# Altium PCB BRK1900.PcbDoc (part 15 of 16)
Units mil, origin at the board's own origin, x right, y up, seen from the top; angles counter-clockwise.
Board outline 8858.27 x 5905.51 mil, 10 copper layers (L1-TOP, L2-GND, L3-PWR, L4-GND, L5-PWR, L6-PWR, L7-GND, L8-SIG, L9-GND, L10-BOT), stack 48.824 mil thick; 456 components, 571 nets, 2296 pads, 2416 vias.
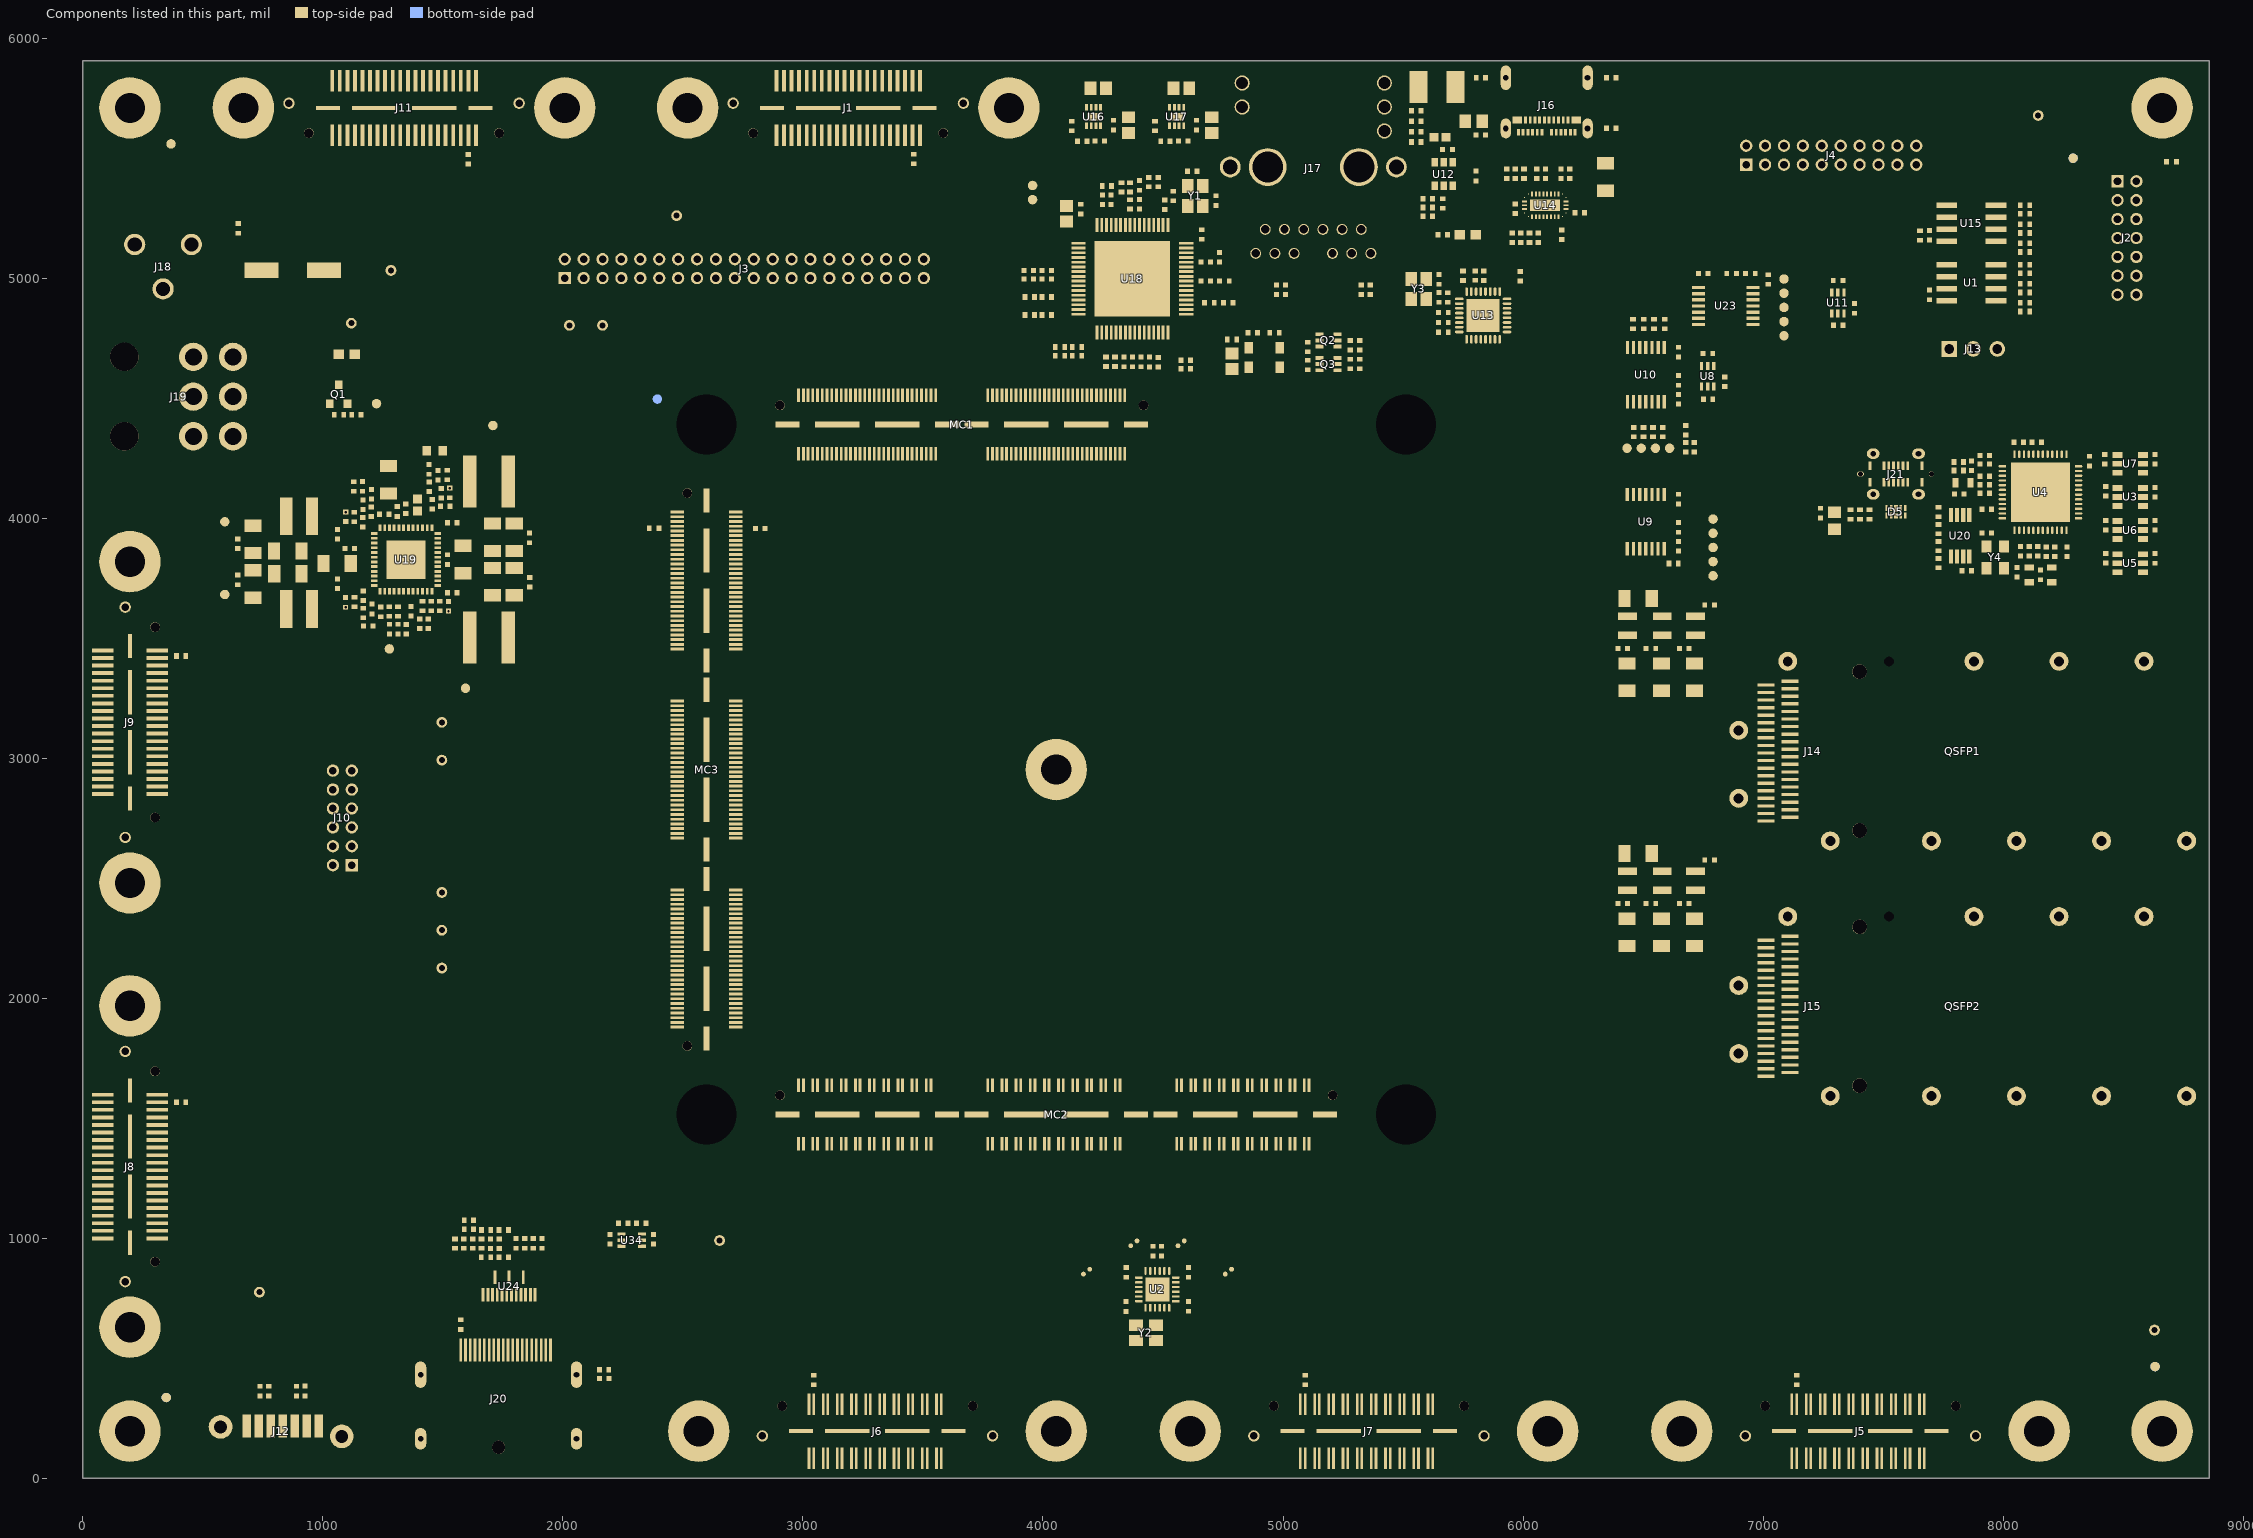
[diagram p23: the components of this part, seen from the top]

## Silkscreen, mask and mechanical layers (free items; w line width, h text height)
Top Overlay:
  circle w22: c201,4873 r11
  region: 5688.98,1078.74 5027.98,1078.74 5027.98,763.78 5688.98,763.78
  lines w4.72: 29.53,4062 738.19,4062 738.19,4822.83 561.02,4822.83 561.02,5374.02 255.91,5374.02 ; 1968.5,1373 1416,1373 1416,1100 2054,1100 2054,1318.9 ; 4749.57,4586.61 1968.5,4586.61 1968.5,1318.9 6377.95,1318.9 6377.95,2373.59 ; 4825.23,4586.61 6377.95,4586.61 6377.95,3478.77 ; 6377.95,2415.78 6377.95,3436.58 ; 6911,5623 7213,5623 ; 7358,5622 7501,5622 ; 255.91,5374.02 29.53,5374.02 255.91,5374.02
  lines w15.75: 139,4873 201,4873 ; 187.32,4835.41 ccw(c201,4873) 187.32,4910.59 ; 241,4873 289,4873
  text "USB 3.0" at 6664.97,5877.3 h100 r180
  text "+1.8V" at 7535,5747 h30 r270
  text "DGND" at 7617,5727 h30 r270
  text "PS CONFIG" at 7007.46,5683.39 h75
  text "DGND" at 7223,5600 h30
  text "VDCIN:" at 30,5467 h30
  text "PROG_B" at 6899.61,5413.38 h30 r270
  text "ERROR_OUT" at 6978.35,5413.38 h30 r270
  text "ERROR_STATUS" at 7057.09,5413.38 h30 r270
  text "SRST_B" at 7135.83,5413.38 h30 r270
  text "DONE" at 7214.57,5413.38 h30 r270
  text "MODE3" at 7303.15,5413.38 h30 r270
  text "MODE2" at 7381.89,5413.38 h30 r270
  text "MODE1" at 7460.63,5413.38 h30 r270
  text "MODE0" at 7539.37,5413.38 h30 r270
  text "INIT_B" at 7618.11,5413.38 h30 r270
  text "6-15 VDC" at 41,5396 h80
  text "+1.8V" at 8659,5391.74 h30
  text "TMS" at 8659,5307.74 h30
  text "JTAG" at 8295.93,5285.05 h75 r270
  text "TCK" at 8659,5231.74 h30
  text "TDO" at 8659,5150.74 h30
  text "I/O BREAKOUT" at 2532.24,5127.95 h40
  text "TDI" at 8659,5075.74 h30
  text "SRST_B" at 8659,4912.74 h30
  text "-" at 380.99,4907.99 h70 r180
  text "Ethernet" at 5341.75,4898.96 h100 r180
  text "+" at 126,4834 h70 r90
  text "DGND" at 7755.91,4645.67 h30 r270
  text "SDA" at 7850.39,4645.67 h30 r270
  text "SCL" at 7948.82,4645.67 h30 r270
  text "USB JTAG" at 7361.03,4315.19 h75
  text "PWR" at 449,4207 h60 r270
  text "GND" at 608.5,4207 h60 r270
  text "QSFP1" at 7034.81,3485.55 h100
  text "I/O BREAKOUT" at 1174,2989.35 h40 r270
  text "QSFP2" at 7034.81,2422.56 h100
  text "'.Part_Number' / '.PCB_Revision'XX" at 3328.36,787.25 h40
  text "DisplayPort / Source" at 1944.88,609.15 h100
  text "SATA" at 668.66,438.31 h100
Dimensions:
  text ":::" at 6846.99,5979 h40 r180
  text ":::" at 2640,5943 h40
  text ":::" at -69,4019 h40 r270
  text ":::" at 8929,3929.69 h40 r90
  text ":::" at -73,1844 h40 r270
  text ":::" at 8929,1220.47 h40 r90
  text ":::" at 2528,-62 h40
  text ":::" at 6350,-67 h40
  text "All dimensions in mm unless otherwise specified" at 9247,-80 h50
Outline:
  the board outline again, w7.87
Mechanical:
  lines w3.94: 1968.46,1318.79 1968.46,4586.51 ; 1968.5,1318.9 6377.95,1318.9 6377.95,4586.61 1968.5,4586.61
Fab Notes:
  drawing of 180 lines, arcs and shapes, not listed
  text "LAYER STACKUP TABLE" at 9476.38,9166.3 h50
  text "M" at 12034.15,9045.9 h73.62
  text "a" at 12088.96,9045.88 h73.62
  text "t" at 12122.69,9045.88 h73.62
  text "e" at 12143.78,9045.88 h73.62
  text "r" at 12181.73,9045.9 h73.62
  text "i" at 12207.03,9045.9 h73.62
  text "a" at 12223.89,9045.88 h73.62
  text "l" at 12257.62,9045.9 h73.62
  text "S" at 13065.26,9042.91 h73.62
  text "i" at 13094.78,9042.91 h73.62
  text "n" at 13111.64,9042.91 h73.62
  text "g" at 13145.43,9042.93 h73.62
  text "l" at 13174.89,9042.91 h73.62
  text "e" at 13191.76,9042.91 h73.62
  text "-" at 13225.49,9042.91 h73.62
  text "E" at 13246.57,9042.92 h73.62
  text "n" at 13276.09,9042.91 h73.62
  text "d" at 13309.82,9042.91 h73.62
  text "e" at 13343.55,9042.91 h73.62
  text "d" at 13377.28,9042.91 h73.62
  text "D" at 13885.94,9042.92 h73.62
  text "i" at 13923.89,9042.91 h73.62
  text "f" at 13940.76,9042.91 h73.62
  text "f" at 13961.84,9042.91 h73.62
  text "e" at 13982.92,9042.91 h73.62
  text "r" at 14016.65,9042.91 h73.62
  text "e" at 14037.74,9042.91 h73.62
  text "n" at 14071.47,9042.91 h73.62
  text "t" at 14105.2,9042.96 h73.62
  text "i" at 14126.29,9042.91 h73.62
  text "a" at 14143.15,9042.91 h73.62
  text "l" at 14172.67,9042.91 h73.62
  text "D" at 14235.26,9042.92 h73.62
  text "i" at 14273.21,9042.91 h73.62
  text "f" at 14290.07,9042.91 h73.62
  text "f" at 14311.16,9042.91 h73.62
  text "e" at 14332.24,9042.91 h73.62
  text "r" at 14365.97,9042.91 h73.62
  text "e" at 14387.05,9042.91 h73.62
  text "n" at 14420.79,9042.91 h73.62
  text "t" at 14454.52,9042.96 h73.62
  text "i" at 14475.6,9042.91 h73.62
  text "a" at 14492.47,9042.91 h73.62
  text "l" at 14521.98,9042.91 h73.62
  text "D" at 14626.66,9042.92 h73.62
  text "i" at 14664.61,9042.91 h73.62
  text "f" at 14681.47,9042.91 h73.62
  text "f" at 14702.56,9042.91 h73.62
  text "e" at 14723.64,9042.91 h73.62
  text "r" at 14757.37,9042.91 h73.62
  text "e" at 14778.46,9042.91 h73.62
  text "n" at 14812.19,9042.91 h73.62
  text "t" at 14845.92,9042.96 h73.62
  text "i" at 14867,9042.91 h73.62
  text "a" at 14883.87,9042.91 h73.62
  text "l" at 14913.39,9042.91 h73.62
  text "D" at 14975.98,9042.92 h73.62
  text "i" at 15013.92,9042.91 h73.62
  text "f" at 15030.79,9042.91 h73.62
  text "f" at 15051.87,9042.91 h73.62
  text "e" at 15072.96,9042.91 h73.62
  text "r" at 15106.69,9042.91 h73.62
  text "e" at 15127.77,9042.91 h73.62
  text "n" at 15161.5,9042.91 h73.62
  text "t" at 15195.24,9042.96 h73.62
  text "i" at 15216.32,9042.91 h73.62
  text "a" at 15233.19,9042.91 h73.62
  text "l" at 15262.7,9042.91 h73.62
  text "P" at 12029.94,8961.56 h73.62
  text "r" at 12072.1,8961.56 h73.62
  text "e" at 12097.4,8961.55 h73.62
  text "s" at 12135.35,8961.55 h73.62
  text "s" at 12169.08,8961.55 h73.62
  text "e" at 12202.82,8961.55 h73.62
  text "d" at 12240.77,8961.55 h73.62
  text "C" at 12375.05,8958.59 h73.62
  text "o" at 12408.78,8958.58 h73.62
  text "p" at 12442.51,8958.59 h73.62
  text "p" at 12476.24,8958.59 h73.62
  text "e" at 12509.98,8958.58 h73.62
  text "r" at 12543.71,8958.58 h73.62
  text "T" at 13170.48,8958.58 h73.62
  text "r" at 13199.99,8958.58 h73.62
  text "a" at 13221.07,8958.58 h73.62
  text "c" at 13250.59,8958.61 h73.62
  text "e" at 13275.89,8958.58 h73.62
  text "S" at 13460.87,8958.58 h73.62
  text "i" at 13490.39,8958.58 h73.62
  text "n" at 13507.25,8958.58 h73.62
  text "g" at 13541.04,8958.6 h73.62
  text "l" at 13570.5,8958.58 h73.62
  text "e" at 13587.37,8958.58 h73.62
  text "-" at 13621.1,8958.58 h73.62
  text "E" at 13642.18,8958.59 h73.62
  text "n" at 13671.7,8958.58 h73.62
  text "d" at 13705.43,8958.58 h73.62
  text "e" at 13739.16,8958.58 h73.62
  text "d" at 13772.9,8958.58 h73.62
  text "T" at 13970.11,8958.58 h73.62
  text "r" at 13999.63,8958.58 h73.62
  text "a" at 14020.71,8958.58 h73.62
  text "c" at 14050.23,8958.61 h73.62
  text "e" at 14075.53,8958.58 h73.62
  text "T" at 14315.22,8958.58 h73.62
  text "r" at 14344.74,8958.58 h73.62
  text "a" at 14365.82,8958.58 h73.62
  text "c" at 14395.34,8958.61 h73.62
  text "e" at 14420.64,8958.58 h73.62
  text "T" at 14710.83,8958.58 h73.62
  text "r" at 14740.35,8958.58 h73.62
  text "a" at 14761.43,8958.58 h73.62
  text "c" at 14790.95,8958.61 h73.62
  text "e" at 14816.25,8958.58 h73.62
  text "T" at 15055.94,8958.58 h73.62
  text "r" at 15085.46,8958.58 h73.62
  text "a" at 15106.54,8958.58 h73.62
  text "c" at 15136.05,8958.61 h73.62
  text "e" at 15161.35,8958.58 h73.62
  text "G" at 10295.99,8877.29 h73.62
  text "e" at 10346.58,8877.22 h73.62
  text "r" at 10384.53,8877.23 h73.62
  text "b" at 10409.83,8877.22 h73.62
  text "e" at 10447.78,8877.22 h73.62
  text "r" at 10485.73,8877.23 h73.62
  text "M" at 11697.46,8877.23 h73.62
  text "a" at 11752.27,8877.22 h73.62
  text "t" at 11786.01,8877.22 h73.62
  text "e" at 11807.09,8877.22 h73.62
  text "r" at 11845.04,8877.23 h73.62
  text "i" at 11870.34,8877.23 h73.62
  text "a" at 11887.2,8877.22 h73.62
  text "l" at 11920.93,8877.23 h73.62
  text "T" at 12000.48,8877.23 h73.62
  text "h" at 12042.64,8877.23 h73.62
  text "i" at 12080.59,8877.23 h73.62
  text "c" at 12097.46,8877.22 h73.62
  text "k" at 12131.19,8877.23 h73.62
  text "n" at 12164.92,8877.23 h73.62
  text "e" at 12202.87,8877.22 h73.62
  text "s" at 12240.82,8877.22 h73.62
  text "s" at 12274.55,8877.22 h73.62
  text "T" at 12341.38,8874.24 h73.62
  text "h" at 12370.89,8874.24 h73.62
  text "i" at 12404.63,8874.24 h73.62
  text "c" at 12421.49,8874.28 h73.62
  text "k" at 12446.79,8874.24 h73.62
  text "n" at 12476.31,8874.24 h73.62
  text "e" at 12510.04,8874.24 h73.62
  text "s" at 12543.77,8874.24 h73.62
  text "s" at 12569.07,8874.24 h73.62
  text "C" at 12707.53,8874.26 h73.62
  text "o" at 12741.26,8874.24 h73.62
  text "p" at 12774.99,8874.25 h73.62
  text "p" at 12808.72,8874.25 h73.62
  text "e" at 12842.46,8874.24 h73.62
  text "r" at 12876.19,8874.24 h73.62
  text "I" at 13094.72,8874.24 h73.62
  text "m" at 13111.59,8874.24 h73.62
  text "p" at 13162.19,8874.25 h73.62
  text "e" at 13195.92,8874.24 h73.62
  text "d" at 13229.65,8874.24 h73.62
  text "a" at 13263.38,8874.24 h73.62
  text "n" at 13292.9,8874.24 h73.62
  text "c" at 13326.63,8874.28 h73.62
  text "e" at 13351.93,8874.24 h73.62
  text "T" at 13477.71,8874.24 h73.62
  text "r" at 13507.22,8874.24 h73.62
  text "a" at 13528.3,8874.24 h73.62
  text "c" at 13557.82,8874.28 h73.62
  text "e" at 13583.12,8874.24 h73.62
  text "W" at 13629.5,8874.24 h73.62
  text "i" at 13688.53,8874.24 h73.62
  text "d" at 13705.4,8874.24 h73.62
  text "t" at 13739.13,8874.3 h73.62
  text "h" at 13760.21,8874.24 h73.62
  text "I" at 13894.36,8874.24 h73.62
  text "m" at 13911.23,8874.24 h73.62
  text "p" at 13961.82,8874.25 h73.62
  text "e" at 13995.56,8874.24 h73.62
  text "d" at 14029.29,8874.24 h73.62
  text "a" at 14063.02,8874.24 h73.62
  text "n" at 14092.54,8874.24 h73.62
  text "c" at 14126.27,8874.28 h73.62
  text "e" at 14151.57,8874.24 h73.62
  text "W" at 14214.21,8874.24 h73.62
  text "i" at 14273.25,8874.24 h73.62
  text "d" at 14290.11,8874.24 h73.62
  text "t" at 14323.84,8874.3 h73.62
  text "h" at 14344.93,8874.24 h73.62
  text "/" at 14378.69,8874.29 h73.62
  text "S" at 14403.96,8874.24 h73.62
  text "p" at 14433.48,8874.25 h73.62
  text "a" at 14467.21,8874.24 h73.62
  text "c" at 14496.72,8874.28 h73.62
  text "e" at 14522.02,8874.24 h73.62
  text "I" at 14635.08,8874.24 h73.62
  text "m" at 14651.94,8874.24 h73.62
  text "p" at 14702.54,8874.25 h73.62
  text "e" at 14736.27,8874.24 h73.62
  text "d" at 14770.01,8874.24 h73.62
  text "a" at 14803.74,8874.24 h73.62
  text "n" at 14833.25,8874.24 h73.62
  text "c" at 14866.99,8874.28 h73.62
  text "e" at 14892.29,8874.24 h73.62
  text "W" at 14954.93,8874.24 h73.62
  text "i" at 15013.96,8874.24 h73.62
  text "d" at 15030.83,8874.24 h73.62
  text "t" at 15064.56,8874.3 h73.62
  text "h" at 15085.65,8874.24 h73.62
  text "/" at 15119.41,8874.29 h73.62
  text "S" at 15144.68,8874.24 h73.62
  text "p" at 15174.19,8874.25 h73.62
  text "a" at 15207.93,8874.24 h73.62
  text "c" at 15237.44,8874.28 h73.62
  text "e" at 15262.74,8874.24 h73.62
  text "L" at 9487.93,8792.9 h73.62
  text "a" at 9525.88,8792.89 h73.62
  text "y" at 9559.61,8792.9 h73.62
  text "e" at 9589.13,8792.89 h73.62
  text "r" at 9627.08,8792.9 h73.62
  text "L" at 9698.36,8792.9 h73.62
  text "a" at 9736.31,8792.89 h73.62
  text "y" at 9770.04,8792.9 h73.62
  text "e" at 9799.56,8792.89 h73.62
  text "r" at 9837.51,8792.9 h73.62
  text "N" at 9879.67,8792.9 h73.62
  text "a" at 9926.05,8792.89 h73.62
  text "m" at 9959.79,8792.9 h73.62
  text "e" at 10010.39,8792.89 h73.62
  text "L" at 10295.99,8792.9 h73.62
  text "a" at 10333.93,8792.89 h73.62
  text "y" at 10367.67,8792.9 h73.62
  text "e" at 10397.18,8792.89 h73.62
  text "r" at 10435.13,8792.9 h73.62
  text "M" at 10548.5,8792.9 h73.62
  text "a" at 10603.32,8792.89 h73.62
  text "t" at 10637.05,8792.89 h73.62
  text "e" at 10658.13,8792.89 h73.62
  text "r" at 10696.08,8792.9 h73.62
  text "i" at 10721.38,8792.9 h73.62
  text "a" at 10738.25,8792.89 h73.62
  text "l" at 10771.98,8792.9 h73.62
  text "T" at 10805.71,8792.9 h73.62
  text "y" at 10847.88,8792.9 h73.62
  text "p" at 10877.39,8792.92 h73.62
  text "e" at 10915.34,8792.89 h73.62
  text "M" at 10981.99,8792.9 h73.62
  text "a" at 11036.81,8792.89 h73.62
  text "t" at 11070.54,8792.89 h73.62
  text "e" at 11091.62,8792.89 h73.62
  text "r" at 11129.57,8792.9 h73.62
  text "i" at 11154.87,8792.9 h73.62
  text "a" at 11171.74,8792.89 h73.62
  text "l" at 11205.47,8792.9 h73.62
  text "C" at 11239.2,8792.9 h73.62
  text "o" at 11285.58,8792.89 h73.62
  text "n" at 11323.53,8792.9 h73.62
  text "s" at 11361.48,8792.89 h73.62
  text "t" at 11395.21,8792.89 h73.62
  text "r" at 11416.3,8792.9 h73.62
  text "u" at 11441.6,8792.89 h73.62
  text "c" at 11479.54,8792.89 h73.62
  text "t" at 11513.28,8792.89 h73.62
  text "i" at 11534.36,8792.9 h73.62
  text "o" at 11551.23,8792.89 h73.62
  text "n" at 11589.17,8792.9 h73.62
  text "E" at 11663.79,8792.9 h73.62
  text "r" at 11705.95,8792.9 h73.62
  text "(" at 11748.12,8792.9 h73.62
  text "1" at 11769.2,8792.9 h73.62
  text "G" at 11819.8,8792.95 h73.62
  text "H" at 11870.4,8792.9 h73.62
  text "z" at 11916.78,8792.9 h73.62
  text ")" at 11950.51,8792.9 h73.62
  text "(" at 12093.07,8792.9 h73.62
  text "m" at 12114.15,8792.9 h73.62
  text "i" at 12164.75,8792.9 h73.62
  text "l" at 12181.62,8792.9 h73.62
  text ")" at 12198.48,8792.9 h73.62
  text "(" at 12404.51,8789.92 h73.62
  text "u" at 12425.59,8789.91 h73.62
  text "m" at 12459.32,8789.91 h73.62
  text ")" at 12509.89,8789.92 h73.62
  text "W" at 12648.61,8789.91 h73.62
  text "e" at 12707.64,8789.91 h73.62
  text "i" at 12741.37,8789.91 h73.62
  text "g" at 12758.29,8789.94 h73.62
  text "h" at 12787.75,8789.91 h73.62
  text "t" at 12821.49,8789.96 h73.62
  text "(" at 12855.22,8789.92 h73.62
  text "o" at 12876.3,8789.91 h73.62
  text "z" at 12910.03,8789.93 h73.62
  text ")" at 12935.3,8789.92 h73.62
  text "(" at 13145.22,8789.92 h73.62
  text "o" at 13166.31,8789.91 h73.62
  text "h" at 13200.04,8789.91 h73.62
  text "m" at 13233.77,8789.91 h73.62
  text "s" at 13284.37,8789.91 h73.62
  text ")" at 13309.64,8789.92 h73.62
  text "(" at 13557.67,8789.92 h73.62
  text "m" at 13578.75,8789.91 h73.62
  text "i" at 13629.35,8789.91 h73.62
  text "l" at 13646.22,8789.91 h73.62
  text "s" at 13663.08,8789.91 h73.62
  text ")" at 13688.35,8789.92 h73.62
  text "(" at 13944.86,8789.92 h73.62
  text "o" at 13965.95,8789.91 h73.62
  text "h" at 13999.68,8789.91 h73.62
  text "m" at 14033.41,8789.91 h73.62
  text "s" at 14084.01,8789.91 h73.62
  text ")" at 14109.27,8789.92 h73.62
  text "(" at 14311.01,8789.92 h73.62
  text "m" at 14332.1,8789.91 h73.62
  text "i" at 14382.69,8789.91 h73.62
  text "l" at 14399.56,8789.91 h73.62
  text "s" at 14416.43,8789.91 h73.62
  text ")" at 14441.69,8789.92 h73.62
  text "(" at 14685.58,8789.92 h73.62
  text "o" at 14706.66,8789.91 h73.62
  text "h" at 14740.4,8789.91 h73.62
  text "m" at 14774.13,8789.91 h73.62
  text "s" at 14824.73,8789.91 h73.62
  text ")" at 14849.99,8789.92 h73.62
  text "(" at 15051.73,8789.92 h73.62
  text "m" at 15072.81,8789.91 h73.62
  text "i" at 15123.41,8789.91 h73.62
  text "l" at 15140.28,8789.91 h73.62
  text "s" at 15157.14,8789.91 h73.62
  text ")" at 15182.41,8789.92 h73.62
  text "O" at 9698.36,8670.61 h69.53
  text "v" at 9748.96,8670.62 h69.53
  text "e" at 9778.48,8670.64 h69.53
  text "r" at 9812.21,8670.62 h69.53
  text "l" at 9833.29,8670.62 h69.53
  text "a" at 9845.94,8670.64 h69.53
  text "y" at 9879.67,8670.62 h69.53
  text "T" at 9926.05,8670.62 h69.53
  text "o" at 9964,8670.64 h69.53
  text "p" at 9997.74,8670.61 h69.53
  text "G" at 10295.99,8670.61 h69.53
  text "T" at 10342.37,8670.62 h69.53
  text "O" at 10380.32,8670.61 h69.53
  text "S" at 10548.5,8670.61 h69.53
  text "i" at 10590.67,8670.62 h69.53
  text "l" at 10603.32,8670.62 h69.53
  text "k" at 10616.02,8670.62 h69.53
  text "s" at 10645.48,8670.64 h69.53
  text "c" at 10679.22,8670.64 h69.53
  text "r" at 10712.95,8670.62 h69.53
  text "e" at 10734.03,8670.64 h69.53
  text "e" at 10767.76,8670.64 h69.53
  text "n" at 10801.5,8670.62 h69.53
  text "S" at 9698.36,8586.27 h69.53
  text "o" at 9740.53,8586.31 h69.53
  text "l" at 9774.26,8586.29 h69.53
  text "d" at 9786.91,8586.31 h69.53
  text "e" at 9820.64,8586.31 h69.53
  text "r" at 9854.37,8586.29 h69.53
  text "M" at 9892.32,8586.29 h69.53
  text "a" at 9938.7,8586.31 h69.53
  text "s" at 9972.44,8586.31 h69.53
  text "k" at 10006.22,8586.29 h69.53
  text "T" at 10052.55,8586.29 h69.53
  text "o" at 10090.5,8586.31 h69.53
  text "p" at 10124.23,8586.27 h69.53
  text "G" at 10295.99,8586.27 h69.53
  text "T" at 10342.37,8586.29 h69.53
  text "S" at 10380.32,8586.27 h69.53
  text "S" at 10548.5,8586.27 h69.53
  text "o" at 10590.67,8586.31 h69.53
  text "l" at 10624.4,8586.29 h69.53
  text "d" at 10637.05,8586.31 h69.53
  text "e" at 10670.78,8586.31 h69.53
  text "r" at 10704.52,8586.29 h69.53
  text "R" at 10742.46,8586.29 h69.53
  text "e" at 10788.85,8586.31 h69.53
  text "s" at 10822.58,8586.31 h69.53
  text "i" at 10856.31,8586.29 h69.53
  text "s" at 10868.96,8586.31 h69.53
  text "t" at 10902.69,8586.31 h69.53
  text "3" at 11781.63,8583.34 h73.62
  text "." at 11811.15,8583.3 h73.62
  text "5" at 11828.01,8583.34 h73.62
  text "1" at 9487.93,8501.96 h69.53
  text "L" at 9698.36,8501.96 h69.53
  text "1" at 9732.09,8501.96 h69.53
  text "-" at 9765.83,8501.96 h69.53
  text "T" at 9786.91,8501.96 h69.53
  text "O" at 9824.86,8501.94 h69.53
  text "P" at 9875.46,8501.96 h69.53
  text "G" at 10295.99,8501.94 h69.53
  text "T" at 10342.37,8501.96 h69.53
  text "L" at 10380.32,8501.96 h69.53
  text "C" at 10548.5,8501.94 h69.53
  text "o" at 10594.89,8501.98 h69.53
  text "p" at 10628.62,8501.94 h69.53
  text "p" at 10662.35,8501.94 h69.53
  text "e" at 10696.08,8501.98 h69.53
  text "r" at 10729.81,8501.96 h69.53
  text "3" at 12400.3,8499.01 h73.62
  text "0" at 12429.81,8499.01 h73.62
  text "-" at 12459.33,8498.99 h73.62
  text "5" at 12480.41,8499.01 h73.62
  text "0" at 12509.93,8499.01 h73.62
  text "1" at 12644.4,8498.99 h73.62
  text "/" at 12673.95,8499 h73.62
  text "3" at 12699.21,8499.01 h73.62
  text "+" at 12741.38,8498.99 h73.62
  text "p" at 12783.54,8499.03 h73.62
  text "l" at 12817.28,8498.97 h73.62
  text "a" at 12834.14,8499.01 h73.62
  text "t" at 12863.66,8498.99 h73.62
  text "i" at 12884.74,8498.97 h73.62
  text "n" at 12901.61,8498.97 h73.62
  text "g" at 12935.34,8499 h73.62
  text "5" at 13212.56,8499.01 h73.62
  text "0" at 13242.08,8499.01 h73.62
  text "4" at 13582.92,8498.97 h73.62
  text "." at 13612.44,8498.97 h73.62
  text "5" at 13629.3,8499.01 h73.62
  text "5" at 13658.82,8499.01 h73.62
  text "9" at 14007.99,8499.01 h73.62
  text "0" at 14037.51,8499.01 h73.62
  text "4" at 14256.3,8498.97 h73.62
  text "." at 14285.82,8498.97 h73.62
  text "0" at 14302.68,8499.01 h73.62
  text "5" at 14332.2,8499.01 h73.62
  text "/" at 14374.4,8499 h73.62
  text "4" at 14412.31,8498.97 h73.62
  text "." at 14441.83,8498.97 h73.62
  text "9" at 14458.7,8499.01 h73.62
  text "5" at 14488.21,8499.01 h73.62
  text "1" at 14736.08,8498.99 h73.62
  text "0" at 14765.6,8499.01 h73.62
  text "0" at 14795.12,8499.01 h73.62
  text "3" at 14997.02,8499.01 h73.62
  text "." at 15026.53,8498.97 h73.62
  text "3" at 15043.4,8499.01 h73.62
  text "0" at 15072.92,8499.01 h73.62
  text "/" at 15115.12,8499 h73.62
  text "5" at 15153.03,8499.01 h73.62
  text "." at 15182.55,8498.97 h73.62
  text "7" at 15199.41,8498.97 h73.62
  text "0" at 15228.93,8499.01 h73.62
  text "P" at 10548.5,8417.63 h69.53
  text "r" at 10590.67,8417.63 h69.53
  text "e" at 10611.75,8417.64 h69.53
  text "p" at 10645.48,8417.61 h69.53
  text "r" at 10679.22,8417.63 h69.53
  text "e" at 10700.3,8417.64 h69.53
  text "g" at 10734.03,8417.63 h69.53
  text "P" at 10981.99,8414.64 h73.62
  text "P" at 11015.72,8414.64 h73.62
  text "(" at 11049.46,8414.68 h73.62
  text "1" at 11070.54,8414.66 h73.62
  text "0" at 11100.05,8414.67 h73.62
  text "8" at 11129.57,8414.67 h73.62
  text "0" at 11159.09,8414.67 h73.62
  text ")" at 11188.62,8414.68 h73.62
  text "R" at 11209.69,8414.64 h73.62
  text "C" at 11243.42,8414.64 h73.62
  text "7" at 11277.15,8414.64 h73.62
  text "1" at 11306.67,8414.66 h73.62
  text "3" at 11781.63,8414.67 h73.62
  text "." at 11811.15,8414.64 h73.62
  text "9" at 11828.01,8414.67 h73.62
  text "2" at 12088.86,8414.66 h73.62
  text "." at 12118.38,8414.64 h73.62
  text "9" at 12135.24,8414.67 h73.62
  text "7" at 12164.76,8414.64 h73.62
  text "2" at 12194.27,8414.66 h73.62
  text "2" at 9487.95,8333.3 h69.53
  text "L" at 9698.36,8333.3 h69.53
  text "2" at 9732.11,8333.3 h69.53
  text "-" at 9765.83,8333.3 h69.53
  text "G" at 9786.91,8333.28 h69.53
  text "N" at 9833.29,8333.3 h69.53
  text "D" at 9875.46,8333.3 h69.53
  text "G" at 10295.99,8333.28 h69.53
  text "1" at 10342.37,8333.3 h69.53
  text "C" at 10548.5,8333.28 h69.53
  text "o" at 10594.89,8333.31 h69.53
  text "p" at 10628.62,8333.28 h69.53
  text "p" at 10662.35,8333.28 h69.53
  text "e" at 10696.08,8333.31 h69.53
  text "r" at 10729.81,8333.3 h69.53
  text "1" at 12438.18,8330.33 h73.62
  text "5" at 12467.69,8330.34 h73.62
  text "1" at 12762.24,8330.33 h73.62
  text "/" at 12791.79,8330.33 h73.62
  text "2" at 12817.05,8330.33 h73.62
  text "C" at 10548.5,8248.95 h69.53
  text "o" at 10594.89,8248.98 h69.53
  text "r" at 10628.62,8248.97 h69.53
  text "e" at 10649.7,8248.98 h69.53
  text "2" at 10981.99,8246 h73.62
  text "*" at 11011.51,8245.96 h73.62
  text "7" at 11041.02,8245.98 h73.62
  text "6" at 11070.54,8246.01 h73.62
  text "2" at 11100.05,8246 h73.62
  text "8" at 11129.57,8246.01 h73.62
  text "(" at 11171.74,8246.02 h73.62
  text "R" at 11192.82,8245.98 h73.62
  text "C" at 11226.55,8245.98 h73.62
  text "5" at 11260.28,8246.01 h73.62
  text "0" at 11289.8,8246.01 h73.62
  text ")" at 11319.33,8246.02 h73.62
  text "4" at 11781.63,8245.98 h73.62
  text "." at 11811.15,8245.98 h73.62
  text "6" at 11828.01,8246.01 h73.62
  text "1" at 12072.03,8246 h73.62
  text "6" at 12101.54,8246.01 h73.62
  text "." at 12131.06,8245.98 h73.62
  text "0" at 12147.92,8246.01 h73.62
  text "0" at 12177.44,8246.01 h73.62
  text "0" at 12206.95,8246.01 h73.62
  text "3" at 9487.93,8164.6 h69.53
  text "L" at 9698.36,8164.64 h69.53
  text "3" at 9732.09,8164.6 h69.53
  text "-" at 9765.83,8164.64 h69.53
  text "S" at 9786.91,8164.62 h69.53
  text "I" at 9829.07,8164.64 h69.53
  text "G" at 9841.72,8164.62 h69.53
  text "1" at 9888.11,8164.64 h69.53
  text "G" at 10295.99,8164.62 h69.53
  text "2" at 10342.38,8164.64 h69.53
  text "C" at 10548.5,8164.62 h69.53
  text "o" at 10594.89,8164.65 h69.53
  text "p" at 10628.62,8164.62 h69.53
  text "p" at 10662.35,8164.62 h69.53
  text "e" at 10696.08,8164.65 h69.53
  text "r" at 10729.81,8164.64 h69.53
  text "1" at 12438.18,8161.66 h73.62
  text "5" at 12467.69,8161.68 h73.62
  text "1" at 12762.24,8161.66 h73.62
  text "/" at 12791.79,8161.67 h73.62
  text "2" at 12817.05,8161.66 h73.62
  text "P" at 10548.5,8080.31 h69.53
  text "r" at 10590.67,8080.31 h69.53
  text "e" at 10611.75,8080.32 h69.53
  text "p" at 10645.48,8080.29 h69.53
  text "r" at 10679.22,8080.31 h69.53
  text "e" at 10700.3,8080.32 h69.53
  text "g" at 10734.03,8080.3 h69.53
  text "P" at 10981.99,8077.32 h73.62
  text "P" at 11015.72,8077.32 h73.62
  text "(" at 11049.46,8077.36 h73.62
  text "1" at 11070.54,8077.33 h73.62
  text "0" at 11100.05,8077.35 h73.62
  text "8" at 11129.57,8077.35 h73.62
  text "0" at 11159.09,8077.35 h73.62
  text ")" at 11188.62,8077.36 h73.62
  text "R" at 11209.69,8077.32 h73.62
  text "C" at 11243.42,8077.32 h73.62
  text "7" at 11277.15,8077.32 h73.62
  text "1" at 11306.67,8077.33 h73.62
  text "3" at 11781.63,8077.35 h73.62
  text "." at 11811.15,8077.32 h73.62
  text "9" at 11828.01,8077.35 h73.62
  text "3" at 12088.86,8077.35 h73.62
  text "." at 12118.38,8077.32 h73.62
  text "0" at 12135.24,8077.35 h73.62
  text "5" at 12164.76,8077.35 h73.62
  text "5" at 12194.27,8077.35 h73.62
  text "4" at 9487.93,7995.98 h69.53
  text "L" at 9698.36,7995.98 h69.53
  text "4" at 9732.09,7995.98 h69.53
  text "-" at 9765.83,7995.98 h69.53
  text "G" at 9786.91,7995.96 h69.53
  text "N" at 9833.29,7995.98 h69.53
  text "D" at 9875.46,7995.98 h69.53
  text "G" at 10295.99,7995.96 h69.53
  text "3" at 10342.37,7995.94 h69.53
  text "C" at 10548.5,7995.96 h69.53
  text "o" at 10594.89,7995.99 h69.53
  text "p" at 10628.62,7995.96 h69.53
  text "p" at 10662.35,7995.96 h69.53
  text "e" at 10696.08,7995.99 h69.53
  text "r" at 10729.81,7995.98 h69.53
  text "1" at 12438.18,7993 h73.62
  text "5" at 12467.69,7993.02 h73.62
  text "1" at 12762.24,7993 h73.62
  text "/" at 12791.79,7993.01 h73.62
  text "2" at 12817.05,7993 h73.62
  text "C" at 10548.5,7911.63 h69.53
  text "o" at 10594.89,7911.66 h69.53
  text "r" at 10628.62,7911.64 h69.53
  text "e" at 10649.7,7911.66 h69.53
  text "2" at 10981.99,7908.67 h73.62
  text "*" at 11011.51,7908.64 h73.62
  text "7" at 11041.02,7908.65 h73.62
  text "6" at 11070.54,7908.69 h73.62
  text "2" at 11100.05,7908.67 h73.62
  text "8" at 11129.57,7908.69 h73.62
  text "(" at 11171.74,7908.7 h73.62
  text "R" at 11192.82,7908.65 h73.62
  text "C" at 11226.55,7908.65 h73.62
  text "5" at 11260.28,7908.69 h73.62
  text "0" at 11289.8,7908.69 h73.62
  text ")" at 11319.33,7908.7 h73.62
  text "4" at 11781.63,7908.65 h73.62
  text "." at 11811.15,7908.65 h73.62
  text "6" at 11828.01,7908.69 h73.62
  text "1" at 12072.03,7908.67 h73.62
  text "6" at 12101.54,7908.69 h73.62
  text "." at 12131.06,7908.65 h73.62
  text "0" at 12147.92,7908.69 h73.62
  text "0" at 12177.44,7908.69 h73.62
  text "0" at 12206.95,7908.69 h73.62
  text "5" at 9487.93,7827.3 h69.53
  text "L" at 9698.36,7827.31 h69.53
  text "5" at 9732.09,7827.3 h69.53
  text "-" at 9765.83,7827.32 h69.53
  text "P" at 9786.91,7827.31 h69.53
  text "W" at 9829.07,7827.31 h69.53
  text "R" at 9892.32,7827.31 h69.53
  text "1" at 9938.7,7827.31 h69.53
  text "G" at 10295.99,7827.3 h69.53
  text "4" at 10342.37,7827.31 h69.53
  text "C" at 10548.5,7827.3 h69.53
  text "o" at 10594.89,7827.33 h69.53
  text "p" at 10628.62,7827.3 h69.53
  text "p" at 10662.35,7827.3 h69.53
  text "e" at 10696.08,7827.33 h69.53
  text "r" at 10729.81,7827.31 h69.53
  text "1" at 12438.18,7824.34 h73.62
  text "5" at 12467.69,7824.36 h73.62
  text "1" at 12762.24,7824.34 h73.62
  text "/" at 12791.79,7824.35 h73.62
  text "2" at 12817.05,7824.34 h73.62
  text "P" at 10548.5,7742.98 h69.53
  text "r" at 10590.67,7742.98 h69.53
  text "e" at 10611.75,7743 h69.53
  text "p" at 10645.48,7742.96 h69.53
  text "r" at 10679.22,7742.98 h69.53
  text "e" at 10700.3,7743 h69.53
  text "g" at 10734.03,7742.98 h69.53
  text "P" at 10981.99,7739.99 h73.62
  text "P" at 11015.72,7739.99 h73.62
  text "(" at 11049.46,7740.04 h73.62
  text "1" at 11070.54,7740.01 h73.62
  text "0" at 11100.05,7740.03 h73.62
  text "8" at 11129.57,7740.03 h73.62
  text "0" at 11159.09,7740.03 h73.62
  text ")" at 11188.62,7740.04 h73.62
  text "R" at 11209.69,7739.99 h73.62
  text "C" at 11243.42,7739.99 h73.62
  text "7" at 11277.15,7739.99 h73.62
  text "1" at 11306.67,7740.01 h73.62
  text "3" at 11781.63,7740.03 h73.62
  text "." at 11811.15,7739.99 h73.62
  text "9" at 11828.01,7740.03 h73.62
  text "3" at 12088.86,7740.03 h73.62
  text "." at 12118.38,7739.99 h73.62
  text "2" at 12135.24,7740.01 h73.62
  text "9" at 12164.76,7740.03 h73.62
  text "1" at 12194.27,7740.01 h73.62
  text "6" at 9487.93,7658.63 h69.53
  text "L" at 9698.36,7658.65 h69.53
  text "6" at 9732.09,7658.63 h69.53
  text "-" at 9765.83,7658.65 h69.53
  text "P" at 9786.91,7658.65 h69.53
  text "W" at 9829.07,7658.65 h69.53
  text "R" at 9892.32,7658.65 h69.53
  text "2" at 9938.72,7658.65 h69.53
  text "G" at 10295.99,7658.63 h69.53
  text "5" at 10342.37,7658.63 h69.53
  text "C" at 10548.5,7658.63 h69.53
  text "o" at 10594.89,7658.67 h69.53
  text "p" at 10628.62,7658.63 h69.53
  text "p" at 10662.35,7658.63 h69.53
  text "e" at 10696.08,7658.67 h69.53
  text "r" at 10729.81,7658.65 h69.53
  text "1" at 12438.18,7655.68 h73.62
  text "5" at 12467.69,7655.7 h73.62
  text "1" at 12762.24,7655.68 h73.62
  text "/" at 12791.79,7655.69 h73.62
  text "2" at 12817.05,7655.68 h73.62
  text "C" at 10548.5,7574.3 h69.53
  text "o" at 10594.89,7574.33 h69.53
  text "r" at 10628.62,7574.32 h69.53
  text "e" at 10649.7,7574.33 h69.53
  text "2" at 10981.99,7571.35 h73.62
  text "*" at 11011.51,7571.31 h73.62
  text "7" at 11041.02,7571.33 h73.62
  text "6" at 11070.54,7571.36 h73.62
  text "2" at 11100.05,7571.35 h73.62
  text "8" at 11129.57,7571.36 h73.62
  text "(" at 11171.74,7571.37 h73.62
  text "R" at 11192.82,7571.33 h73.62
  text "C" at 11226.55,7571.33 h73.62
  text "5" at 11260.28,7571.36 h73.62
  text "0" at 11289.8,7571.36 h73.62
  text ")" at 11319.33,7571.37 h73.62
  text "4" at 11781.63,7571.33 h73.62
  text "." at 11811.15,7571.33 h73.62
  text "6" at 11828.01,7571.36 h73.62
  text "1" at 12072.03,7571.35 h73.62
  text "6" at 12101.54,7571.36 h73.62
  text "." at 12131.06,7571.33 h73.62
  text "0" at 12147.92,7571.36 h73.62
  text "0" at 12177.44,7571.36 h73.62
  text "0" at 12206.95,7571.36 h73.62
  text "7" at 9487.93,7489.99 h69.53
  text "L" at 9698.36,7489.99 h69.53
  text "7" at 9732.09,7489.99 h69.53
  text "-" at 9765.83,7489.99 h69.53
  text "G" at 9786.91,7489.97 h69.53
  text "N" at 9833.29,7489.99 h69.53
  text "D" at 9875.46,7489.99 h69.53
  text "G" at 10295.99,7489.97 h69.53
  text "6" at 10342.37,7489.97 h69.53
  text "C" at 10548.5,7489.97 h69.53
  text "o" at 10594.89,7490 h69.53
  text "p" at 10628.62,7489.97 h69.53
  text "p" at 10662.35,7489.97 h69.53
  text "e" at 10696.08,7490 h69.53
  text "r" at 10729.81,7489.99 h69.53
  text "1" at 12438.18,7487.02 h73.62
  text "5" at 12467.69,7487.03 h73.62
  text "1" at 12762.24,7487.02 h73.62
  text "/" at 12791.79,7487.02 h73.62
  text "2" at 12817.05,7487.02 h73.62
  text "P" at 10548.5,7405.66 h69.53
  text "r" at 10590.67,7405.66 h69.53
  text "e" at 10611.75,7405.67 h69.53
  text "p" at 10645.48,7405.64 h69.53
  text "r" at 10679.22,7405.66 h69.53
  text "e" at 10700.3,7405.67 h69.53
  text "g" at 10734.03,7405.66 h69.53
  text "P" at 10981.99,7402.67 h73.62
  text "P" at 11015.72,7402.67 h73.62
  text "(" at 11049.46,7402.71 h73.62
  text "1" at 11070.54,7402.69 h73.62
  text "0" at 11100.05,7402.7 h73.62
  text "8" at 11129.57,7402.7 h73.62
  text "0" at 11159.09,7402.7 h73.62
  text ")" at 11188.62,7402.71 h73.62
  text "R" at 11209.69,7402.67 h73.62
  text "C" at 11243.42,7402.67 h73.62
  text "7" at 11277.15,7402.67 h73.62
  text "1" at 11306.67,7402.69 h73.62
  text "3" at 11781.63,7402.7 h73.62
  text "." at 11811.15,7402.67 h73.62
  text "9" at 11828.01,7402.7 h73.62
  text "3" at 12088.86,7402.7 h73.62
  text "." at 12118.38,7402.67 h73.62
  text "0" at 12135.24,7402.7 h73.62
  text "5" at 12164.76,7402.7 h73.62
  text "5" at 12194.27,7402.7 h73.62
  text "8" at 9487.93,7321.31 h69.53
  text "L" at 9698.36,7321.33 h69.53
  text "8" at 9732.09,7321.31 h69.53
  text "-" at 9765.83,7321.33 h69.53
  text "S" at 9786.91,7321.31 h69.53
  text "I" at 9829.07,7321.33 h69.53
  text "G" at 9841.72,7321.31 h69.53
  text "2" at 9888.12,7321.33 h69.53
  text "G" at 10295.99,7321.31 h69.53
  text "7" at 10342.37,7321.33 h69.53
  text "C" at 10548.5,7321.31 h69.53
  text "o" at 10594.89,7321.34 h69.53
  text "p" at 10628.62,7321.31 h69.53
  text "p" at 10662.35,7321.31 h69.53
  text "e" at 10696.08,7321.34 h69.53
  text "r" at 10729.81,7321.33 h69.53
  text "1" at 12438.18,7318.35 h73.62
  text "5" at 12467.69,7318.37 h73.62
  text "1" at 12762.24,7318.35 h73.62
  text "/" at 12791.79,7318.36 h73.62
  text "2" at 12817.05,7318.35 h73.62
  text "5" at 13212.56,7318.37 h73.62
  text "0" at 13242.08,7318.37 h73.62
  text "4" at 13582.92,7318.34 h73.62
  text "." at 13612.44,7318.34 h73.62
  text "0" at 13629.3,7318.37 h73.62
  text "5" at 13658.82,7318.37 h73.62
  text "1" at 14736.08,7318.35 h73.62
  text "0" at 14765.6,7318.37 h73.62
  text "0" at 14795.12,7318.37 h73.62
  text "3" at 14997.02,7318.37 h73.62
  text "." at 15026.53,7318.34 h73.62
  text "1" at 15043.4,7318.35 h73.62
  text "5" at 15072.92,7318.37 h73.62
  text "/" at 15115.12,7318.36 h73.62
  text "5" at 15153.03,7318.37 h73.62
  text "." at 15182.55,7318.34 h73.62
  text "8" at 15199.41,7318.37 h73.62
  text "5" at 15228.93,7318.37 h73.62
  text "C" at 10548.5,7236.98 h69.53
  text "o" at 10594.89,7237.01 h69.53
  text "r" at 10628.62,7237 h69.53
  text "e" at 10649.7,7237.01 h69.53
  text "2" at 10981.99,7234.02 h73.62
  text "*" at 11011.51,7233.99 h73.62
  text "7" at 11041.02,7234.01 h73.62
  text "6" at 11070.54,7234.04 h73.62
  text "2" at 11100.05,7234.02 h73.62
  text "8" at 11129.57,7234.04 h73.62
  text "(" at 11171.74,7234.05 h73.62
  text "R" at 11192.82,7234.01 h73.62
  text "C" at 11226.55,7234.01 h73.62
  text "5" at 11260.28,7234.04 h73.62
  text "0" at 11289.8,7234.04 h73.62
  text ")" at 11319.33,7234.05 h73.62
  text "4" at 11781.63,7234.01 h73.62
  text "." at 11811.15,7234.01 h73.62
  text "6" at 11828.01,7234.04 h73.62
  text "1" at 12072.03,7234.02 h73.62
  text "6" at 12101.54,7234.04 h73.62
  text "." at 12131.06,7234.01 h73.62
  text "0" at 12147.92,7234.04 h73.62
  text "0" at 12177.44,7234.04 h73.62
  text "0" at 12206.95,7234.04 h73.62
  text "9" at 9487.93,7152.65 h69.53
  text "L" at 9698.36,7152.66 h69.53
  text "9" at 9732.09,7152.65 h69.53
  text "-" at 9765.83,7152.67 h69.53
  text "G" at 9786.91,7152.65 h69.53
  text "N" at 9833.29,7152.66 h69.53
  text "D" at 9875.46,7152.66 h69.53
  text "G" at 10295.99,7152.65 h69.53
  text "8" at 10342.37,7152.65 h69.53
  text "C" at 10548.5,7152.65 h69.53
  text "o" at 10594.89,7152.68 h69.53
  text "p" at 10628.62,7152.65 h69.53
  text "p" at 10662.35,7152.65 h69.53
  text "e" at 10696.08,7152.68 h69.53
  text "r" at 10729.81,7152.66 h69.53
  text "1" at 12438.18,7149.69 h73.62
  text "5" at 12467.69,7149.71 h73.62
  text "1" at 12762.24,7149.69 h73.62
  text "/" at 12791.79,7149.7 h73.62
  text "2" at 12817.05,7149.69 h73.62
  text "P" at 10548.5,7068.33 h69.53
  text "r" at 10590.67,7068.33 h69.53
  text "e" at 10611.75,7068.35 h69.53
  text "p" at 10645.48,7068.32 h69.53
  text "r" at 10679.22,7068.33 h69.53
  text "e" at 10700.3,7068.35 h69.53
  text "g" at 10734.03,7068.33 h69.53
  text "P" at 10981.99,7065.34 h73.62
  text "P" at 11015.72,7065.34 h73.62
  text "(" at 11049.46,7065.39 h73.62
  text "1" at 11070.54,7065.36 h73.62
  text "0" at 11100.05,7065.38 h73.62
  text "8" at 11129.57,7065.38 h73.62
  text "0" at 11159.09,7065.38 h73.62
  text ")" at 11188.62,7065.39 h73.62
  text "R" at 11209.69,7065.34 h73.62
  text "C" at 11243.42,7065.34 h73.62
  text "7" at 11277.15,7065.34 h73.62
  text "1" at 11306.67,7065.36 h73.62
  text "3" at 11781.63,7065.38 h73.62
  text "." at 11811.15,7065.34 h73.62
  text "9" at 11828.01,7065.38 h73.62
  text "2" at 12088.86,7065.36 h73.62
  text "." at 12118.38,7065.34 h73.62
  text "9" at 12135.24,7065.38 h73.62
  text "7" at 12164.76,7065.34 h73.62
  text "2" at 12194.27,7065.36 h73.62
  text "1" at 9487.93,6984 h69.53
  text "0" at 9521.66,6983.99 h69.53
  text "L" at 9698.36,6984 h69.53
  text "1" at 9732.09,6984 h69.53
  text "0" at 9765.83,6983.99 h69.53
  text "-" at 9799.56,6984.01 h69.53
  text "B" at 9820.64,6984 h69.53
  text "O" at 9862.81,6983.99 h69.53
  text "T" at 9913.41,6984 h69.53
  text "G" at 10295.99,6983.99 h69.53
  text "B" at 10342.37,6984 h69.53
  text "L" at 10384.53,6984 h69.53
  text "C" at 10548.5,6983.99 h69.53
  text "o" at 10594.89,6984.02 h69.53
  text "p" at 10628.62,6983.99 h69.53
  text "p" at 10662.35,6983.99 h69.53
  text "e" at 10696.08,6984.02 h69.53
  text "r" at 10729.81,6984 h69.53
  text "3" at 12400.3,6981.05 h73.62
  text "0" at 12429.81,6981.05 h73.62
  text "-" at 12459.33,6981.03 h73.62
  text "5" at 12480.41,6981.05 h73.62
  text "0" at 12509.93,6981.05 h73.62
  text "1" at 12644.4,6981.03 h73.62
  text "/" at 12673.95,6981.04 h73.62
  text "3" at 12699.21,6981.05 h73.62
  text "+" at 12741.38,6981.03 h73.62
  text "p" at 12783.54,6981.07 h73.62
  text "l" at 12817.28,6981.01 h73.62
  text "a" at 12834.14,6981.05 h73.62
  text "t" at 12863.66,6981.03 h73.62
  text "i" at 12884.74,6981.01 h73.62
  text "n" at 12901.61,6981.01 h73.62
  text "g" at 12935.34,6981.04 h73.62
  text "5" at 13212.56,6981.05 h73.62
  text "0" at 13242.08,6981.05 h73.62
  text "4" at 13582.92,6981.01 h73.62
  text "." at 13612.44,6981.01 h73.62
  text "5" at 13629.3,6981.05 h73.62
  text "5" at 13658.82,6981.05 h73.62
  text "9" at 14007.99,6981.05 h73.62
  text "0" at 14037.51,6981.05 h73.62
  text "4" at 14256.3,6981.01 h73.62
  text "." at 14285.82,6981.01 h73.62
  text "0" at 14302.68,6981.05 h73.62
  text "5" at 14332.2,6981.05 h73.62
  text "/" at 14374.4,6981.04 h73.62
  text "4" at 14412.31,6981.01 h73.62
  text "." at 14441.83,6981.01 h73.62
  text "9" at 14458.7,6981.05 h73.62
  text "5" at 14488.21,6981.05 h73.62
  text "1" at 14736.08,6981.03 h73.62
  text "0" at 14765.6,6981.05 h73.62
  text "0" at 14795.12,6981.05 h73.62
  text "3" at 14997.02,6981.05 h73.62
  text "." at 15026.53,6981.01 h73.62
  text "3" at 15043.4,6981.05 h73.62
  text "0" at 15072.92,6981.05 h73.62
  text "/" at 15115.12,6981.04 h73.62
  text "5" at 15153.03,6981.05 h73.62
  text "." at 15182.55,6981.01 h73.62
  text "7" at 15199.41,6981.01 h73.62
  text "0" at 15228.93,6981.05 h73.62
  text "S" at 9698.36,6899.65 h69.53
  text "o" at 9740.53,6899.69 h69.53
  text "l" at 9774.26,6899.67 h69.53
  text "d" at 9786.91,6899.69 h69.53
  text "e" at 9820.64,6899.69 h69.53
  text "r" at 9854.37,6899.67 h69.53
  text "M" at 9892.32,6899.67 h69.53
  text "a" at 9938.7,6899.69 h69.53
  text "s" at 9972.44,6899.69 h69.53
  text "k" at 10006.22,6899.67 h69.53
  text "B" at 10052.55,6899.67 h69.53
  text "o" at 10094.72,6899.69 h69.53
  text "t" at 10128.45,6899.69 h69.53
  text "t" at 10145.32,6899.69 h69.53
  text "o" at 10162.18,6899.69 h69.53
  text "m" at 10195.96,6899.67 h69.53
  text "G" at 10295.99,6899.65 h69.53
  text "B" at 10342.37,6899.67 h69.53
  text "S" at 10384.53,6899.65 h69.53
  text "S" at 10548.5,6899.65 h69.53
  text "o" at 10590.67,6899.69 h69.53
  text "l" at 10624.4,6899.67 h69.53
  text "d" at 10637.05,6899.69 h69.53
  text "e" at 10670.78,6899.69 h69.53
  text "r" at 10704.52,6899.67 h69.53
  text "R" at 10742.46,6899.67 h69.53
  text "e" at 10788.85,6899.69 h69.53
  text "s" at 10822.58,6899.69 h69.53
  text "i" at 10856.31,6899.67 h69.53
  text "s" at 10868.96,6899.69 h69.53
  text "t" at 10902.69,6899.69 h69.53
  text "3" at 11781.63,6896.72 h73.62
  text "." at 11811.15,6896.68 h73.62
  text "5" at 11828.01,6896.72 h73.62
  text "O" at 9698.36,6815.32 h69.53
  text "v" at 9748.96,6815.34 h69.53
  text "e" at 9778.48,6815.36 h69.53
  text "r" at 9812.21,6815.34 h69.53
  text "l" at 9833.29,6815.34 h69.53
  text "a" at 9845.94,6815.36 h69.53
  text "y" at 9879.67,6815.34 h69.53
  text "B" at 9926.05,6815.34 h69.53
  text "o" at 9968.22,6815.36 h69.53
  text "t" at 10001.95,6815.36 h69.53
  text "t" at 10018.82,6815.36 h69.53
  text "o" at 10035.69,6815.36 h69.53
  text "m" at 10069.47,6815.34 h69.53
  text "G" at 10295.99,6815.32 h69.53
  text "B" at 10342.37,6815.34 h69.53
  text "O" at 10384.53,6815.32 h69.53
  text "S" at 10548.5,6815.32 h69.53
  text "i" at 10590.67,6815.34 h69.53
  text "l" at 10603.32,6815.34 h69.53
  text "k" at 10616.02,6815.34 h69.53
  text "s" at 10645.48,6815.36 h69.53
  text "c" at 10679.22,6815.36 h69.53
  text "r" at 10712.95,6815.34 h69.53
  text "e" at 10734.03,6815.36 h69.53
  text "e" at 10767.76,6815.36 h69.53
  text "n" at 10801.5,6815.34 h69.53
  text "NOTES: /  / 1. MATERIAL: /    IT-180A or equivalent /    Surface finish: ENIG /    Overall thickness: 90 mils +/-10% /  / 2. Fabricate to IPC-6012 (latest revision), Class II /  / 3. SOLDER RESIST: Glossy blue LPI applied over bare copper or gold/nickel plating /  / 4. SILKSCREEN: White /  / 5. LOT CODE IDENTIFICATION: /    Supplier must add identifier and lot code date to silkscreen. /    LOT CODE DATE FORMAT: YYWW (YY = 2-digit year, WW = 2-digit week) /  / 6. Drill sizes are finished size after plating /  / 7. 100% electrical bare board test required for continuity /  / 8. IMPEDANCE CONTROL: /    See Layer Stackup Table on this drawing and refer to '.Part_Number'-PCBStackup.pdf /    Short trace impedance measurements may default to TDR coupons. /  / 9. PANELIZATION: /    1 piece per array /    Tab routing required. Tab locations indicated by ::: (see Dimensions Gerber layer) /    0.25-inch rails on all sides /  / 10. POFV: All vias 10-mil diameter and smaller must be plated over filled via using non-conductive epoxy /  / 11. ROHS: Fabricate to meet EU RoHS directive. Supplier must add lead-free marking in silkscreen. /  / 12. UL certification mark required (94V-0) /  / 13. Remove all non-functional pads from internal layers" at -275.59,5962.39 h50
Bottom Assembly:
  text "NOTES /  / 1. SOLDER QSFP1 AND QSFP2 IN EIGHT PLACES ON BOTTOM SIDE AS INDICATED." at 5775.59,6027.56 h50
Mechanical 7:
  circle w10: c7279.56,1592.62 r74.01
  circle w10: c7279.54,2655.61 r74.01
  circle w10: c8586.65,2340.65 r74.01
  circle w10: c8763.81,1592.62 r74.01
  circle w10: c8763.8,2655.61 r74.01
  circle w10: c8586.63,3403.65 r74.01
  circle w10: c7102.39,2340.65 r74.01
  circle w10: c7102.38,3403.65 r74.01
  lines w10: 8501.96,3843.96 8586.96,3758.96 8586.96,3478.76
  text "SOLDER ON BOTTOM SIDE / (8 PLACES)" at 8480.31,3622.05 h60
